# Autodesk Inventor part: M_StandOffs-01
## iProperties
Company: Autodes, Inc
Created: 2005-03
Part Number: M_StandOffs-01
Document SubType Name: Modeling
Density: 1 g/cm^3
Author: Admin
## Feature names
1. Extrusion1
